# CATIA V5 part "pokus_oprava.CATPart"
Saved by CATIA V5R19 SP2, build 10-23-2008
Part number: Part1
Bounding box of the stored display mesh (mm): x 0 to 79.896, y -15 to 15, z -15 to 21.936
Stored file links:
  D:\Catia fórum\Modely\pokus_oprava.CATPart
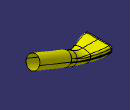
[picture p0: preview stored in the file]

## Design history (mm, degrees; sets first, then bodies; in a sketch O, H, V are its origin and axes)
AxisSystem1: origin (0, 0, 0), X (1, 0, 0), Y (0, 1, 0), Z (0, 0, 1)
Set1
  Sketch1 "Profil_1" on YZ plane of AxisSystem1, origin (0, 0, 0), H (0, 1, 0), V (0, 0, 1)
    point P1 (-15, 0)
    line L1 (-15, 0) -> (15, 0)
    line L2 (15, 0) -> (15, -6)
    line L3 (-15, 0) -> (-15, -6)
    arc A1 centre (0, 2) radius 17 from (-15, -6) to (15, -6) ccw
    point P5 (0, 2)
    length L1 = 30
    distance A1 L1 = 15
    length L3 = 6
    coincidence: P1 H, P5 V
    horizontal: L1 H
    vertical: L2 V, L3 V
    symmetry: L3 L2 V
  Sketch2 on ZX plane of AxisSystem1, origin (0, 0, 0), H (0, 0, 1), V (1, 0, 0)
    axis line L1 (0, 40) -> (20.6879, 91.2044)
    point P1 (0, 40)
    line L2 (-6.9539, 42.8095) -> (8.0304, 79.8969)
    point P4 (8.0304, 79.8969)
    construction line L3 (0, 40) -> (-6.9539, 42.8095)
    line L4 (14.9843, 77.0874) -> (8.0304, 79.8969)
    point P5 (8.0304, 79.8969)
    point P6 (14.9843, 77.0874)
    distance P1 H = 40
    distance P1 V = 0
    angle L1 V = 22
    length L2 = 40
    "Radius" L2 L1 = 7.5
    perpendicularity: L3 L1
    parallelism: L4 L3
    coincidence: P5 L2, P5 P4, P6 L1
  Revol1: Element1 Sketch2, Angle1 360
  Sketch3 "Up+Low" on ZX plane of AxisSystem1, origin (0, 0, 0), H (0, 0, 1), V (1, 0, 0)
    line L1 (0, 0) -> (0, 18.9732)
    point P1 (0, 18.9732)
    reference projected line E1 (8.0304, 79.8969) -> (21.9381, 74.2778) from edge [face of Revol1 from Sketch2.L4 | face of Revol1 from Sketch2.L2]
    reference projected line E2 (-6.9539, 42.8095) -> (6.9539, 37.1905) from edge of Revol1
    point P4 (-6.9539, 42.8095)
    line L2 (21.9381, 74.2778) -> (6.9539, 37.1905)
    arc A1 centre (-21.4965, 48.6852) radius 30.6848 from (6.9539, 37.1905) to (3.8316, 31.3635) cw
    arc A2 centre (21.9491, 18.9732) radius 21.9491 from (3.8316, 31.3635) to (0, 18.9732) ccw
    point P9 (0, 18.9732)
    line L3 (8.0304, 79.8969) -> (-6.9539, 42.8095)
    construction line L4 (0, 0) -> (-15, 0)
    construction line L5 (-15, 0) -> (-15, -11.1911)
    curve C1
    curve C2
    construction line L6 (6.9539, 37.1905) -> (-6.9539, 42.8095)
    point P12 (-6.9539, 42.8095)
    point P13 (-6.9539, 42.8095)
    arc A3 centre (95.4991, 1.4158) radius 110.4991 from (-6.9539, 42.8095) to (-15, 1.4158) ccw
    line L7 (-15, 1.4158) -> (-15, 0)
    curve C3
    length L4 = 15
    vertical: L1 V, L5 V
    perpendicularity: L2 E2
    tangency: A1 L2, A2 L1, A2 A1, A3 L5, A3 L3
    coincidence: P9 P1, P4 P12, P13 P12
    parallelism: L3 L2, L6 E1
    horizontal: L4 H
  Sketch4 on ZX plane of AxisSystem1, origin (0, 0, 0), H (0, 0, 1), V (1, 0, 0)
    axis line L1 (-29.8294, 0) -> (25.1618, 0)
    point P1 (-29.8294, 0)
    line L2 (-18.1234, 15) -> (0, 15)
    point P4 (0, 15)
    line L3 (-18.1234, 15) -> (-18.1234, 0)
    point P5 (-18.1234, 0)
    line L4 (0, 15) -> (0, 0)
    "Radius" L2 L1 = 15
    coincidence: P1 H, P4 V, P5 L1
    horizontal: L1 H, L2 H
    vertical: L3 V, L4 V
  Revol2: Element1 Sketch4, Angle1 360
  Extrude1: Element1 Sketch1, Lim1 20, Lim2 20
  Trim1: Trimmed (Extrude1; Revol2)
  Extrude2: Element1 Sketch3.C2, Lim1 20, Lim2 20, Direction edge [YZ plane of AxisSystem1 | XY plane of AxisSystem1]
  Trim2: Trimmed (Extrude2; Trim1)
  Loft1: Sections (edge of Revol1; Sketch1), StartSectionTangent Revol1, EndSectionTangent Trim2, Guides (Sketch3.C2; Sketch3.C1)
  Fillet1: radius 2, on edge [face of Loft1 | face of Loft1]
  Join1: Elements edge [face of Revol1 from Sketch2.L4 | face of Revol1 from Sketch2.L2]
  Set2 "Oprava"
    Line1: type Normal, RefPoint Sketch2.P6, RefSkin Revol1, Start 0, End 40
    Sweep1: type Circle, Guide Line1, Radius 7.5
    Extremum1: Reference edge of Sweep1, Direction edge [ZX plane of AxisSystem1 | YZ plane of AxisSystem1], Direction2 (0, 0, 1), Direction3 (0, 0, 1)
    Loft2: Sections (edge of Sweep1; Sketch1), StartSectionTangent Sweep1, EndSectionTangent Trim1, Guides (Sketch3.C1; Sketch3.C2)
    Fillet2: radius 2, on edge [face of Loft2 | face of Loft2] (x4)
    Join2: Elements (Fillet2; Sweep1)
Body1 (main body)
